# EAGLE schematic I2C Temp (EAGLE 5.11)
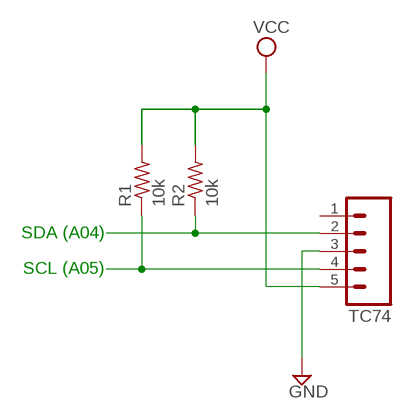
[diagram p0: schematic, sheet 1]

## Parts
R1  10k  R-US_0204/7  [0204/7]
R2  10k  R-US_0204/7  [0204/7]
TC74  M05  [05P]

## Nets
GND: TC74.3
N$1: R2.1 TC74.2
N$3: R1.1 TC74.4
VCC: R1.2 R2.2 TC74.5
Unconnected: TC74.1

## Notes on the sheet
- SDA (A04)
- SCL (A05)

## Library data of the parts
R1 R2 = rcl:R-US_: RESISTOR, American symbol
TC74 = con-amp-quick:M05: AMP QUICK CONNECTOR; OC_FARNELL: unknown; OC_NEWARK: unknown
